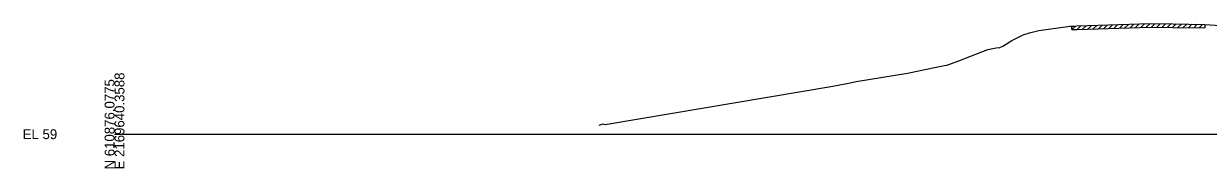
# Model space of a CAD drawing. Extents: x -26 to 6803, y -10 to 19606.
# Drawn here: x 1974.3 to 2309.3, y 7490.3 to 7531.4 of the extents above; entities that cross this region are included whole.
import ezdxf

# ---------------------------------------------------------------- set-up
doc = ezdxf.new("R2010")
doc.units = 0
for name, color, linetype in [('RD_GPK_XS_Cell', 7, 'Continuous'), ('RD_XS_ExGround', 7, 'Continuous'), ('RD_XS_ExPaveRet', 7, 'Continuous')]:
    doc.layers.add(name, color=color, linetype=linetype)

msp = doc.modelspace()

# ---------------------------------------------------------------- linework, layer by layer
at = {"layer": 'RD_GPK_XS_Cell'}
msp.add_line((2000, 7500), (2400, 7500), dxfattribs=at)
at = {"layer": 'RD_XS_ExGround'}
msp.add_lwpolyline([(2137.02, 7502.6), (2138.21, 7502.94), (2138.71, 7502.71), (2203.11, 7513.66), (2207.58, 7514.47), (2209.75, 7514.92), (2224.27, 7517.33), (2225.24, 7517.52), (2231.4, 7518.77), (2234.75, 7519.47), (2235.35, 7519.6), (2235.98, 7519.8), (2239.29, 7521), (2240.22, 7521.35), (2247.02, 7524.04), (2247.49, 7524.13), (2249.32, 7524.47), (2250.37, 7524.58), (2251.25, 7525), (2253.8, 7526.55), (2257.01, 7528.18), (2258.76, 7528.72), (2261.42, 7529.45), (2270.29, 7530.6), (2270.74, 7530.64), (2271.69, 7530.67), (2272.18, 7530.69), (2292.98, 7531.35), (2299.29, 7531.27), (2308.33, 7531.13), (2315.73, 7530.64)], dxfattribs=at)
at = {"layer": 'RD_XS_ExPaveRet'}
for p, q in [((2270.74, 7529.64), (2271.77, 7530.67)), ((2270.74, 7529.64), (2270.74, 7530.64)), ((2270.74, 7529.64), (2271.69, 7529.67)), ((2271.69, 7529.67), (2272.18, 7529.69)), ((2272.18, 7529.69), (2292.98, 7530.35)), ((2272.24, 7529.69), (2273.27, 7530.72)), ((2273.74, 7529.74), (2274.77, 7530.77)), ((2275.24, 7529.78), (2276.27, 7530.82)), ((2276.74, 7529.83), (2277.77, 7530.86)), ((2278.24, 7529.88), (2279.27, 7530.91)), ((2279.74, 7529.93), (2280.77, 7530.96)), ((2281.24, 7529.98), (2282.27, 7531.01)), ((2282.74, 7530.02), (2283.77, 7531.06)), ((2284.24, 7530.07), (2285.27, 7531.1)), ((2285.74, 7530.12), (2286.77, 7531.15)), ((2287.24, 7530.17), (2288.27, 7531.2)), ((2288.74, 7530.22), (2289.77, 7531.25)), ((2290.24, 7530.26), (2291.27, 7531.3)), ((2291.74, 7530.31), (2292.77, 7531.34)), ((2292.98, 7530.35), (2299.29, 7530.27)), ((2293.24, 7530.35), (2294.22, 7531.33)), ((2294.74, 7530.33), (2295.72, 7531.32)), ((2296.24, 7530.31), (2297.22, 7531.3)), ((2297.74, 7530.29), (2298.72, 7531.28)), ((2299.24, 7530.27), (2300.22, 7531.25)), ((2299.29, 7530.27), (2308.33, 7530.13)), ((2300.74, 7530.25), (2301.72, 7531.23)), ((2302.24, 7530.22), (2303.22, 7531.21)), ((2303.74, 7530.2), (2304.72, 7531.19)), ((2305.24, 7530.18), (2306.22, 7531.16)), ((2306.74, 7530.16), (2307.72, 7531.14)), ((2308.33, 7531.13), (2308.33, 7530.13))]:
    msp.add_line(p, q, dxfattribs=at)

# ---------------------------------------------------------------- texts
at = {"layer": 'RD_GPK_XS_Cell'}
for s, p in [('N 610876.0775', (2000, 7490)), ('E 2169640.3588', (2002.8, 7490))]:
    msp.add_text(s, height=2.8, rotation=90, dxfattribs=at).set_placement(p)
msp.add_text('EL 59', height=2.8, dxfattribs=at).set_placement((1974, 7498.6))

doc.saveas('drawing.dxf')
